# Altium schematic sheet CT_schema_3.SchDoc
size 556 x 411 mm
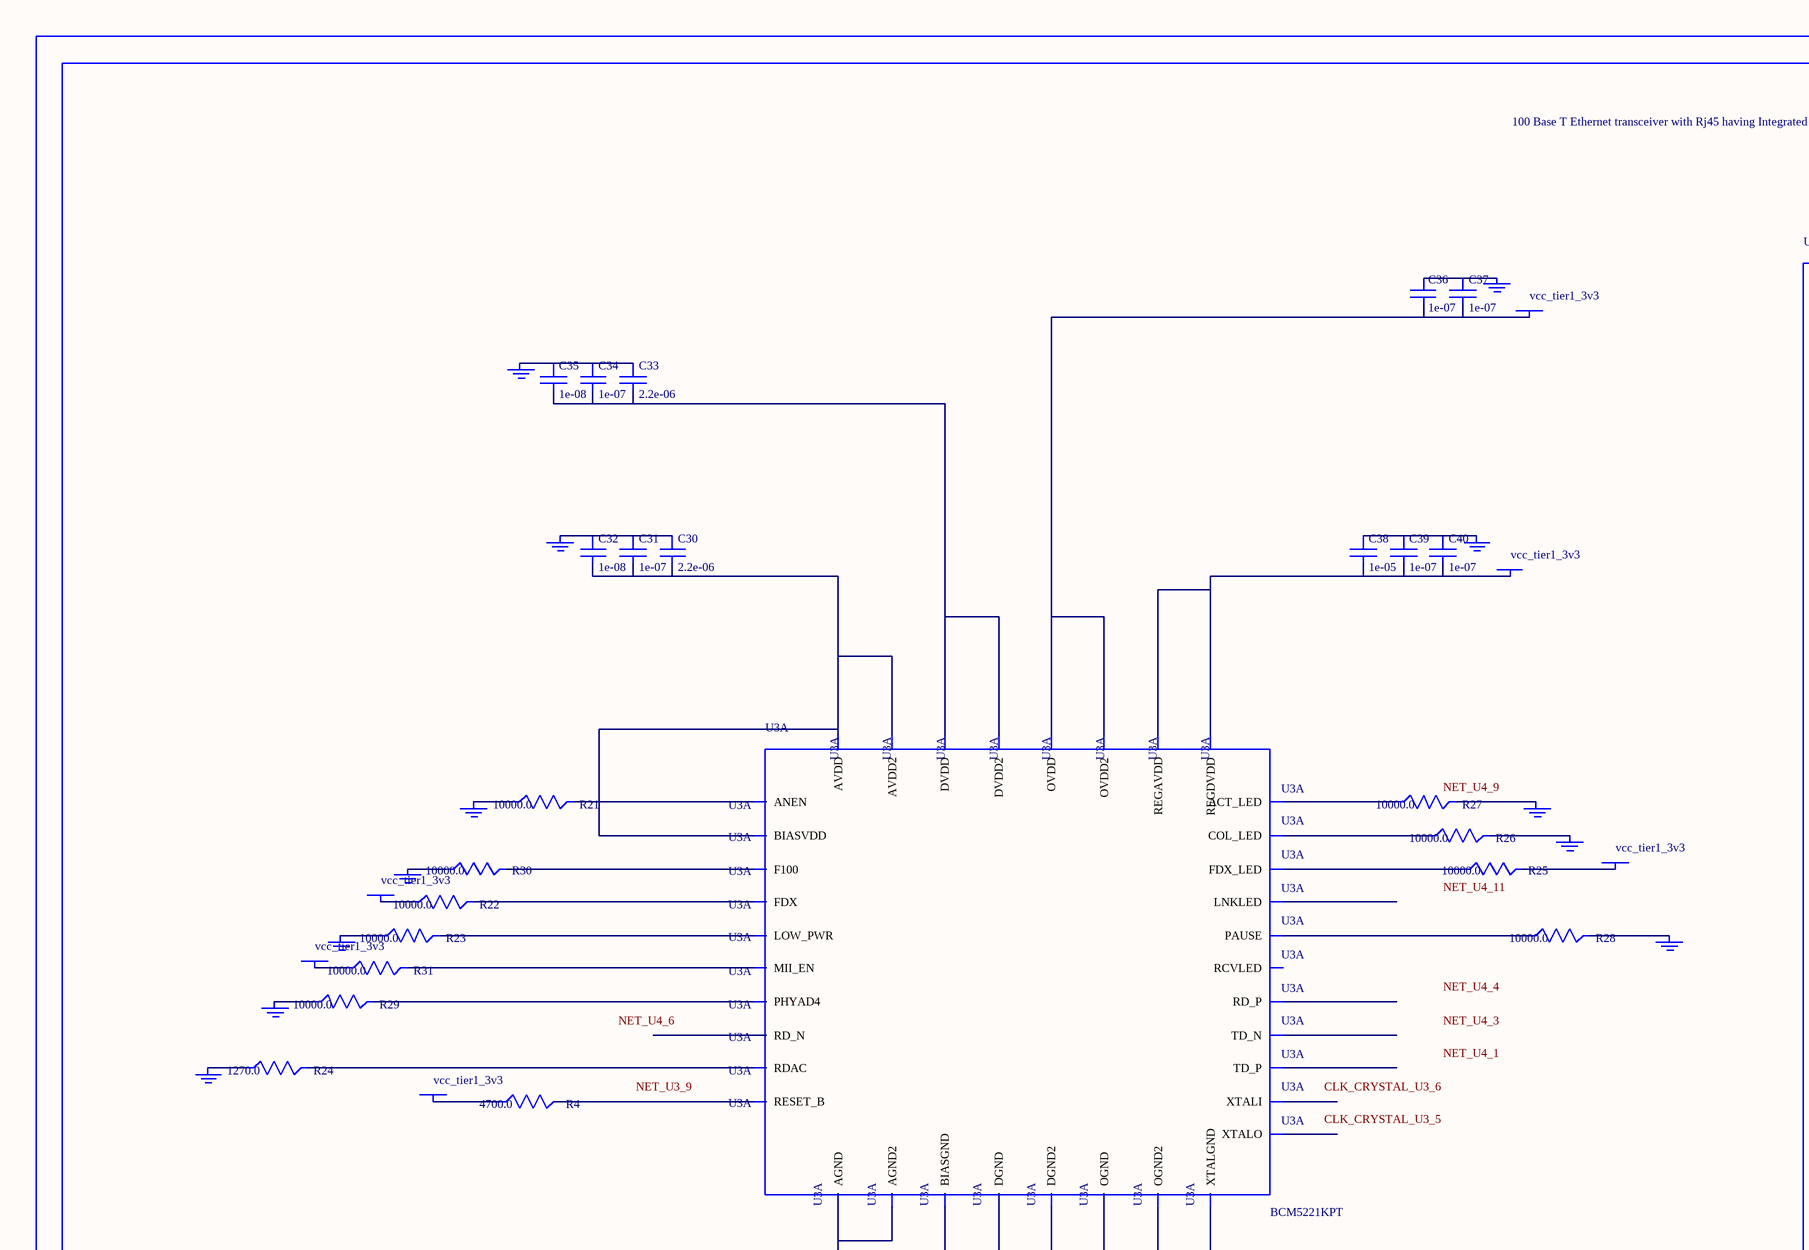
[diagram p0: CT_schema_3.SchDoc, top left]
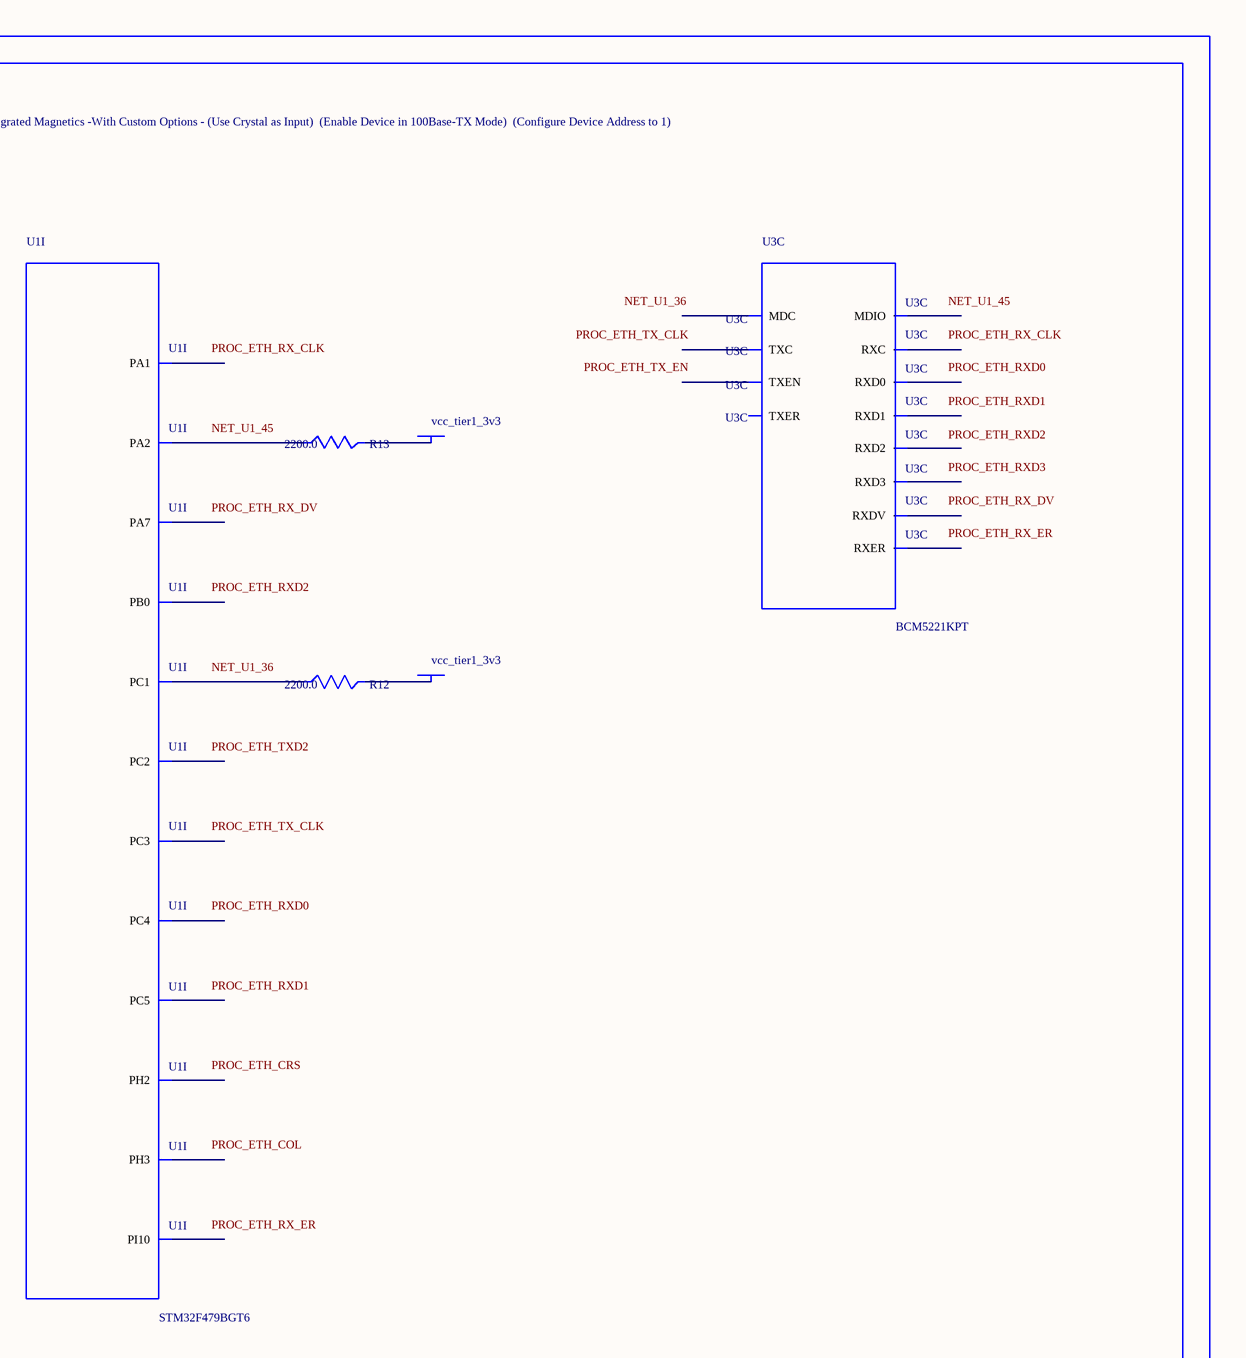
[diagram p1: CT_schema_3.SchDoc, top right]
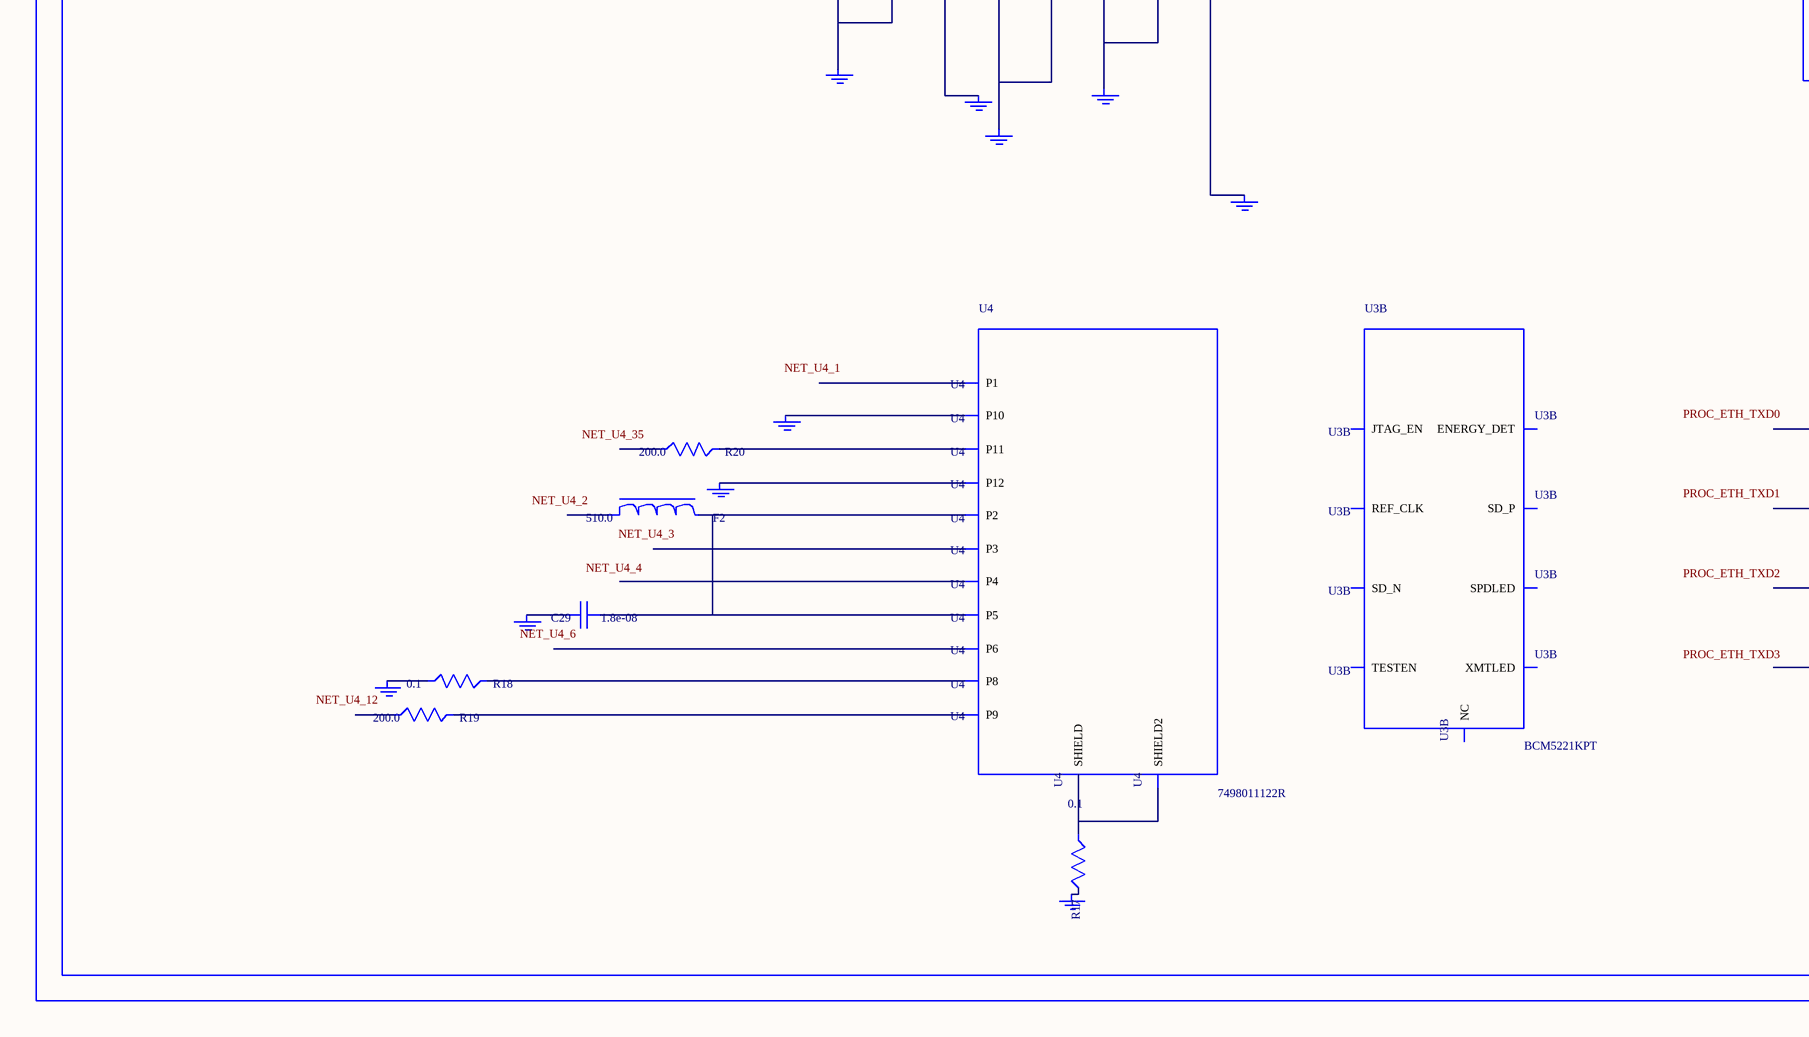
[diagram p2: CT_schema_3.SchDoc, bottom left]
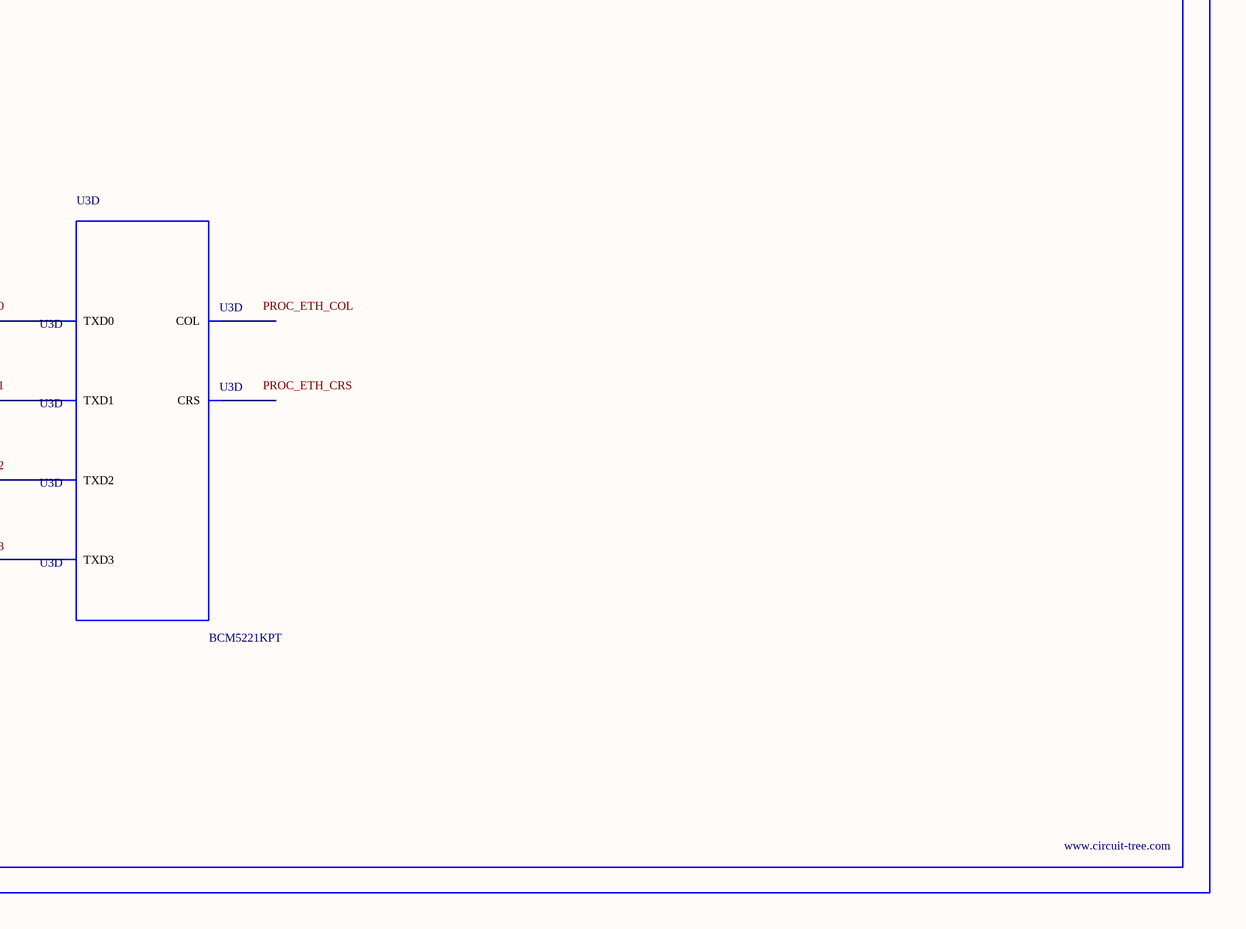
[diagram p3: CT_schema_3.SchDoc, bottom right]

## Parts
BORDER2  (no value)
C29  1.8e-08  [C0402]
C30  2.2e-06  [C0603]
C31  1e-07  [C0402]
C32  1e-08  [C0402]
C33  2.2e-06  [C0603]
C34  1e-07  [C0402]
C35  1e-08  [C0402]
C36  1e-07  [C0402]
C37  1e-07  [C0402]
C38  1e-05  [C0805]
C39  1e-07  [C0402]
C40  1e-07  [C0402]
F2  510.0  [L0603]
GND_INSTANCE_2_0  (no value)
GND_INSTANCE_2_1  (no value)
GND_INSTANCE_2_2  (no value)
GND_INSTANCE_2_3  (no value)
GND_INSTANCE_2_4  (no value)
GND_INSTANCE_2_5  (no value)
GND_INSTANCE_2_6  (no value)
GND_INSTANCE_2_7  (no value)
GND_INSTANCE_2_8  (no value)
GND_INSTANCE_2_9  (no value)
GND_INSTANCE_2_10  (no value)
GND_INSTANCE_2_11  (no value)
GND_INSTANCE_2_12  (no value)
GND_INSTANCE_2_13  (no value)
GND_INSTANCE_2_14  (no value)
GND_INSTANCE_2_15  (no value)
GND_INSTANCE_2_16  (no value)
GND_INSTANCE_2_17  (no value)
GND_INSTANCE_2_18  (no value)
GND_INSTANCE_2_19  (no value)
GND_INSTANCE_2_20  (no value)
GND_INSTANCE_2_21  (no value)
POWER_INSTANCE_2_0  vcc_tier1_3v3
POWER_INSTANCE_2_1  vcc_tier1_3v3
POWER_INSTANCE_2_2  vcc_tier1_3v3
POWER_INSTANCE_2_3  vcc_tier1_3v3
POWER_INSTANCE_2_4  vcc_tier1_3v3
POWER_INSTANCE_2_5  vcc_tier1_3v3
POWER_INSTANCE_2_6  vcc_tier1_3v3
POWER_INSTANCE_2_7  vcc_tier1_3v3
R4  4700.0  [R0603]
R12  2200.0  [R0603]
R13  2200.0  [R0603]
R17  0.1  [R0603]
R18  0.1  [R0603]
R19  200.0  [R0603]
R20  200.0  [R0603]
R21  10000.0  [R0603]
R22  10000.0  [R0603]
R23  10000.0  [R0603]
R24  1270.0  [R0603]
R25  10000.0  [R0603]
R26  10000.0  [R0603]
R27  10000.0  [R0603]
R28  10000.0  [R0603]
R29  10000.0  [R0603]
R30  10000.0  [R0603]
R31  10000.0  [R0603]
U1  STM32F479BGT6  [LQFP208]  (part I of 16)
U3  BCM5221KPT  [TQFP64_10X10MC]  (parts A,B,C,D of 4)
U4  7498011122R  [7498011122R]

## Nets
NetC29_1: C29.1 F2.2 U4.2(P2) U4.5(P5)
NetC29_2: C29.2 GND_INSTANCE_2_17.0(GND)
NetC30_1: C30.1 C31.1 C32.1 GND_INSTANCE_2_11.0(GND)
NetC30_2: C30.2 C31.2 C32.2 U3.22(BIASVDD) U3.27(AVDD) U3.28(AVDD2)
NetC33_1: C33.1 C34.1 C35.1 GND_INSTANCE_2_1.0(GND)
NetC33_2: C33.2 C34.2 C35.2 U3.2(DVDD) U3.55(DVDD2)
NetC36_1: C36.1 C37.1 GND_INSTANCE_2_0.0(GND)
NetC36_2: C36.2 C37.2 POWER_INSTANCE_2_0.0(PWR) U3.1(OVDD) U3.46(OVDD2)
NetC38_1: C38.1 C39.1 C40.1 GND_INSTANCE_2_2.0(GND)
NetC38_2: C38.2 C39.2 C40.2 POWER_INSTANCE_2_1.0(PWR) U3.3(REGDVDD) U3.20(REGAVDD)
NetGND_INSTANCE_2_3_0: GND_INSTANCE_2_3.0(GND) U3.7(XTALGND)
NetGND_INSTANCE_2_4_0: GND_INSTANCE_2_4.0(GND) R26.2
NetGND_INSTANCE_2_5_0: GND_INSTANCE_2_5.0(GND) R27.2
NetGND_INSTANCE_2_6_0: GND_INSTANCE_2_6.0(GND) R28.2
NetGND_INSTANCE_2_7_0: GND_INSTANCE_2_7.0(GND) R29.1
NetGND_INSTANCE_2_8_0: GND_INSTANCE_2_8.0(GND) R23.1
NetGND_INSTANCE_2_9_0: GND_INSTANCE_2_9.0(GND) R24.1
NetGND_INSTANCE_2_10_0: GND_INSTANCE_2_10.0(GND) U3.24(BIASGND)
NetGND_INSTANCE_2_12_0: GND_INSTANCE_2_12.0(GND) R30.1
NetGND_INSTANCE_2_13_0: GND_INSTANCE_2_13.0(GND) R21.1
NetGND_INSTANCE_2_14_0: GND_INSTANCE_2_14.0(GND) U3.29(AGND) U3.32(AGND2)
NetGND_INSTANCE_2_15_0: GND_INSTANCE_2_15.0(GND) U3.40(OGND) U3.45(OGND2)
NetGND_INSTANCE_2_16_0: GND_INSTANCE_2_16.0(GND) U3.54(DGND) U3.63(DGND2)
NetGND_INSTANCE_2_18_0: GND_INSTANCE_2_18.0(GND) R18.1
NetGND_INSTANCE_2_19_0: GND_INSTANCE_2_19.0(GND) U4.10(P10)
NetGND_INSTANCE_2_20_0: GND_INSTANCE_2_20.0(GND) U4.12(P12)
NetGND_INSTANCE_2_21_0: GND_INSTANCE_2_21.0(GND) R17.2
NetPOWER_INSTANCE_2_2_0: POWER_INSTANCE_2_2.0(PWR) R25.2
NetPOWER_INSTANCE_2_3_0: POWER_INSTANCE_2_3.0(PWR) R31.1
NetPOWER_INSTANCE_2_4_0: POWER_INSTANCE_2_4.0(PWR) R22.1
NetPOWER_INSTANCE_2_5_0: POWER_INSTANCE_2_5.0(PWR) R4.1
NetPOWER_INSTANCE_2_6_0: POWER_INSTANCE_2_6.0(PWR) R12.2
NetPOWER_INSTANCE_2_7_0: POWER_INSTANCE_2_7.0(PWR) R13.2
NetR4_2: R4.2 U3.9(RESET_B)
NetR12_1: R12.1 U1.36(PC1)
NetR13_1: R13.1 U1.45(PA2)
NetR17_1: R17.1 U4.13(SHIELD) U4.14(SHIELD2)
NetR18_2: R18.2 U4.8(P8)
NetR19_2: R19.2 U4.9(P9)
NetR20_2: R20.2 U4.11(P11)
NetR21_2: R21.2 U3.38(ANEN)
NetR22_2: R22.2 U3.39(FDX)
NetR23_2: R23.2 U3.16(LOW_PWR)
NetR24_2: R24.2 U3.23(RDAC)
NetR25_1: R25.1 U3.10(FDX_LED)
NetR26_1: R26.1 U3.11(COL_LED)
NetR27_1: R27.1 U3.12(ACT_LED)
NetR28_1: R28.1 U3.13(PAUSE)
NetR29_2: R29.2 U3.14(PHYAD4)
NetR30_2: R30.2 U3.37(F100)
NetR31_2: R31.2 U3.18(MII_EN)

Not connected (* = marked no-connect by the designer): F2 1; R19 1; R20 1; U1 12(PI10) 37(PC2) 38(PC3) 44(PA1) 46(PH2) 47(PH3) 56(PA7) 57(PC4) 58(PC5) 61(PB0); U3 4(REF_CLK) 5(XTALO) 6(XTALI) 8(NC) 15(TESTEN) 17(ENERGY_DET) 19(SD_N) 21(SD_P) 25(RD_N) 26(RD_P) 30(TD_N) 31(TD_P) 33(RCVLED) 34(XMTLED) 35(LNKLED) 36(SPDLED) 41(MDIO) 42(MDC) 43(RXD3) 44(RXD2) 47(RXD1) 48(RXD0) 49(RXDV) 50(RXC) 51(RXER) 52(TXER) 53(TXC) 56(TXEN) 57(TXD0) 58(TXD1) 59(TXD2) 60(TXD3) 61(COL) 62(CRS) 64(JTAG_EN); U4 1(P1) 3(P3) 4(P4) 6(P6)

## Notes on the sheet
- Labels drawn without touching a wire or pin: CLK_CRYSTAL_U3_5, CLK_CRYSTAL_U3_6, NET_U1_36, NET_U1_45, NET_U3_9, NET_U4_1, NET_U4_2, NET_U4_3, NET_U4_4, NET_U4_6, NET_U4_9, NET_U4_11, NET_U4_12, NET_U4_35, PROC_ETH_COL, PROC_ETH_CRS, PROC_ETH_RX_CLK, PROC_ETH_RX_DV, PROC_ETH_RX_ER, PROC_ETH_RXD0, PROC_ETH_RXD1, PROC_ETH_RXD2, PROC_ETH_RXD3, PROC_ETH_TX_CLK, PROC_ETH_TX_EN, PROC_ETH_TXD0, PROC_ETH_TXD1, PROC_ETH_TXD2, PROC_ETH_TXD3

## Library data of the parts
BORDER2 = BORDER_PAGE2
C29 = C0402C183K3RAC
C30 C33 = C0603C225K8RACTU
C31 C34 C36 C37 C39 C40 = C0402C104K3RACTU
C32 C35 = C0402C103K3RAC
C38 = C0805C106K8RACTU
F2 = ERA3APB511V
GND_INSTANCE_2_0-GND_INSTANCE_2_21 = GND
POWER_INSTANCE_2_0-POWER_INSTANCE_2_7 = PWR
R4 = RC0603JR-074K7L
R12 R13 = RC0603JR-072K2L
R17 R18 = ERJ-3RSFR10V
R19 R20 = RC0603JR-07200RL
R21-R23 R25-R31 = RC0603JR-0710KL
R24 = RC0603FR-071K27L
